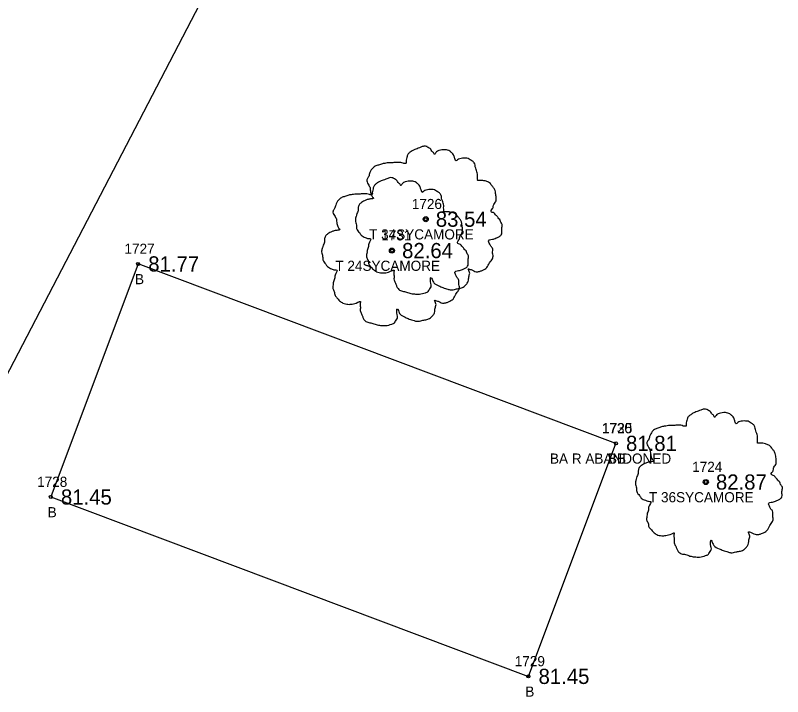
# Model space of a CAD drawing. Extents: x 2139392 to 2143384, y 505395 to 510520.
# Drawn here: x 2141179.8 to 2141255.5, y 509366.5 to 509433.7 of the extents above; entities that cross this region are included whole.
import ezdxf

# ---------------------------------------------------------------- set-up
doc = ezdxf.new("R2010")
doc.units = 0
for name, color, linetype in [('RD_EX_Bldg', 7, 'Continuous'), ('RD_EX_Bldg_txCode', 7, 'Continuous'), ('RD_EX_Fence_Other', 7, 'Continuous'), ('RD_EX_TX_Bldg_ELEV', 7, 'Continuous'), ('RD_EX_TX_VEG_ELEV', 7, 'Continuous'), ('RD_EX_VEG', 7, 'Continuous'), ('RD_EX_VEG_txCode', 7, 'Continuous'), ('RD_SMD_Locator', 7, 'Continuous')]:
    doc.layers.add(name, color=color, linetype=linetype)

msp = doc.modelspace()

# ---------------------------------------------------------------- linework, layer by layer
at = {"layer": 'RD_EX_Bldg'}
msp.add_lwpolyline([(2141239.059, 509391.502), (2141191.916, 509409.201), (2141183.3, 509386.211), (2141230.429, 509368.517), (2141239.059, 509391.502)], dxfattribs=at)
at = {"layer": 'RD_EX_Fence_Other'}
msp.add_lwpolyline([(2141244.956, 509535.084), (2141227.835, 509492.247), (2141166.832, 509374.977), (2141164.262, 509373.907), (2141120.57, 509389.846)], dxfattribs=at)
at = {"layer": 'RD_EX_VEG'}
for centre, radius in [((2141220.293, 509413.615), 0.25), ((2141220.28, 509413.596), 0.0001), ((2141216.967, 509410.519), 0.25), ((2141216.954, 509410.5), 0.0001), ((2141247.934, 509387.689), 0.25), ((2141247.921, 509387.67), 0.0001)]:
    msp.add_circle(centre, radius, dxfattribs=at)
for points in [[(2141220.425, 509420.782), (2141220.125, 509420.807), (2141219.8, 509420.707), (2141219.55, 509420.607), (2141219.325, 509420.532), (2141219.1, 509420.432), (2141218.8, 509420.257), (2141218.575, 509420.057), (2141218.45, 509419.807), (2141218.4, 509419.582), (2141218.351, 509419.308), (2141218.351, 509419.133), (2141218.226, 509419.108), (2141218.076, 509419.133), (2141217.826, 509419.208), (2141217.576, 509419.208), (2141217.326, 509419.208), (2141216.976, 509419.183), (2141216.626, 509419.183), (2141216.351, 509419.133), (2141216.027, 509419.083), (2141215.652, 509418.958), (2141215.302, 509418.833), (2141215.002, 509418.583), (2141214.752, 509418.108), (2141214.627, 509417.758), (2141214.477, 509417.508), (2141214.627, 509417.059), (2141214.802, 509416.709), (2141214.827, 509416.509), (2141214.902, 509416.084), (2141215.002, 509415.859), (2141215.127, 509415.659), (2141215.052, 509415.634), (2141214.677, 509415.584), (2141214.377, 509415.484), (2141213.952, 509415.259), (2141213.728, 509415.034), (2141213.628, 509414.709), (2141213.603, 509414.36), (2141213.503, 509414.16), (2141213.428, 509413.885), (2141213.403, 509413.81), (2141213.353, 509413.485), (2141213.453, 509413.035), (2141213.478, 509412.685), (2141213.603, 509412.46), (2141213.753, 509412.286), (2141213.927, 509412.036), (2141214.327, 509411.811), (2141214.652, 509411.711), (2141214.852, 509411.686), (2141214.677, 509411.186), (2141214.627, 509410.836), (2141214.502, 509410.436), (2141214.502, 509410.361), (2141214.452, 509409.887), (2141214.602, 509409.562), (2141214.677, 509409.187), (2141214.852, 509408.962), (2141215.127, 509408.662), (2141215.452, 509408.437), (2141215.952, 509408.312), (2141216.351, 509408.337), (2141216.926, 509408.512), (2141217.176, 509408.587), (2141217.151, 509408.412), (2141217.176, 509408.037), (2141217.176, 509407.613), (2141217.326, 509407.288), (2141217.426, 509407.013), (2141217.576, 509406.763), (2141217.901, 509406.538), (2141218.301, 509406.463), (2141218.725, 509406.313), (2141219.175, 509406.238), (2141219.675, 509406.213), (2141220.275, 509406.363), (2141220.55, 509406.488), (2141220.65, 509406.663), (2141220.849, 509407.038), (2141220.799, 509407.263), (2141220.824, 509407.863), (2141220.924, 509407.688), (2141221.099, 509407.338), (2141221.599, 509407.038), (2141221.999, 509406.863), (2141222.474, 509406.713), (2141222.774, 509406.638), (2141223.248, 509406.713), (2141223.623, 509406.788), (2141223.998, 509406.913), (2141224.298, 509407.188), (2141224.473, 509407.463), (2141224.523, 509407.738), (2141224.598, 509408.112), (2141224.648, 509408.287)], [(2141224.648, 509408.287), (2141224.573, 509408.462), (2141224.523, 509408.712), (2141224.598, 509408.687), (2141224.773, 509408.637), (2141225.048, 509408.512), (2141225.273, 509408.437), (2141225.597, 509408.462), (2141225.872, 509408.562), (2141226.322, 509408.837), (2141226.597, 509409.312), (2141226.872, 509409.712), (2141226.947, 509410.037), (2141226.897, 509410.261), (2141226.872, 509410.761), (2141226.672, 509411.011), (2141226.622, 509411.136), (2141226.522, 509411.536), (2141226.597, 509411.586), (2141226.872, 509411.636), (2141227.247, 509411.761), (2141227.522, 509411.886), (2141227.746, 509412.061), (2141227.821, 509412.286), (2141227.796, 509412.685), (2141227.846, 509413.085), (2141227.771, 509413.235), (2141227.671, 509413.385), (2141227.596, 509413.585), (2141227.447, 509413.735), (2141227.347, 509413.885), (2141227.247, 509413.985), (2141227.122, 509414.135), (2141226.947, 509414.26), (2141226.797, 509414.31), (2141226.747, 509414.46), (2141226.897, 509414.66), (2141226.947, 509414.759), (2141226.972, 509414.984), (2141227.197, 509415.334), (2141227.247, 509415.734), (2141227.197, 509416.159), (2141227.147, 509416.434), (2141226.997, 509416.709), (2141226.797, 509416.959), (2141226.672, 509417.133), (2141226.497, 509417.258), (2141226.172, 509417.383), (2141225.922, 509417.433), (2141225.572, 509417.433), (2141225.372, 509417.483), (2141225.397, 509417.533), (2141225.397, 509417.683), (2141225.397, 509417.958), (2141225.322, 509418.408), (2141225.173, 509418.908), (2141225.173, 509418.933), (2141225.073, 509419.183), (2141224.848, 509419.382), (2141224.673, 509419.482), (2141224.473, 509419.607), (2141224.223, 509419.632), (2141223.923, 509419.632), (2141223.648, 509419.582), (2141223.448, 509419.482), (2141223.273, 509419.357), (2141223.198, 509419.507), (2141223.098, 509419.807), (2141223.048, 509419.957), (2141222.899, 509420.132), (2141222.674, 509420.332), (2141222.224, 509420.457), (2141221.599, 509420.382), (2141221.299, 509420.182), (2141221.149, 509420.007), (2141221.099, 509420.132), (2141220.899, 509420.332), (2141220.799, 509420.507), (2141220.625, 509420.632), (2141220.475, 509420.732), (2141220.375, 509420.782)], [(2141217.099, 509417.687), (2141216.799, 509417.712), (2141216.474, 509417.612), (2141216.224, 509417.512), (2141215.999, 509417.437), (2141215.775, 509417.337), (2141215.475, 509417.162), (2141215.25, 509416.962), (2141215.125, 509416.712), (2141215.075, 509416.487), (2141215.025, 509416.212), (2141215.025, 509416.037), (2141214.9, 509416.012), (2141214.75, 509416.037), (2141214.5, 509416.112), (2141214.25, 509416.112), (2141214, 509416.112), (2141213.65, 509416.087), (2141213.301, 509416.087), (2141213.026, 509416.037), (2141212.701, 509415.987), (2141212.326, 509415.862), (2141211.976, 509415.737), (2141211.676, 509415.487), (2141211.426, 509415.013), (2141211.301, 509414.663), (2141211.152, 509414.413), (2141211.301, 509413.963), (2141211.476, 509413.613), (2141211.501, 509413.413), (2141211.576, 509412.989), (2141211.676, 509412.764), (2141211.801, 509412.564), (2141211.726, 509412.539), (2141211.351, 509412.489), (2141211.052, 509412.389), (2141210.627, 509412.164), (2141210.402, 509411.939), (2141210.302, 509411.614), (2141210.277, 509411.264), (2141210.177, 509411.064), (2141210.102, 509410.79), (2141210.077, 509410.715), (2141210.027, 509410.39), (2141210.127, 509409.94), (2141210.152, 509409.59), (2141210.277, 509409.365), (2141210.427, 509409.19), (2141210.602, 509408.94), (2141211.002, 509408.715), (2141211.326, 509408.615), (2141211.526, 509408.591), (2141211.351, 509408.091), (2141211.301, 509407.741), (2141211.177, 509407.341), (2141211.177, 509407.266), (2141211.127, 509406.791), (2141211.276, 509406.466), (2141211.351, 509406.092), (2141211.526, 509405.867), (2141211.801, 509405.567), (2141212.126, 509405.342), (2141212.626, 509405.217), (2141213.026, 509405.242), (2141213.601, 509405.417), (2141213.85, 509405.492), (2141213.825, 509405.317), (2141213.85, 509404.942), (2141213.85, 509404.517), (2141214, 509404.192), (2141214.1, 509403.918), (2141214.25, 509403.668), (2141214.575, 509403.443), (2141214.975, 509403.368), (2141215.4, 509403.218), (2141215.85, 509403.143), (2141216.349, 509403.118), (2141216.949, 509403.268), (2141217.224, 509403.393), (2141217.324, 509403.568), (2141217.524, 509403.943), (2141217.474, 509404.167), (2141217.499, 509404.767), (2141217.599, 509404.592), (2141217.774, 509404.242), (2141218.273, 509403.943), (2141218.673, 509403.768), (2141219.148, 509403.618), (2141219.448, 509403.543), (2141219.923, 509403.618), (2141220.298, 509403.693), (2141220.672, 509403.818), (2141220.972, 509404.092), (2141221.147, 509404.367), (2141221.197, 509404.642), (2141221.272, 509405.017), (2141221.322, 509405.192)], [(2141221.322, 509405.192), (2141221.247, 509405.367), (2141221.197, 509405.617), (2141221.272, 509405.592), (2141221.447, 509405.542), (2141221.722, 509405.417), (2141221.947, 509405.342), (2141222.272, 509405.367), (2141222.547, 509405.467), (2141222.996, 509405.742), (2141223.271, 509406.217), (2141223.546, 509406.616), (2141223.621, 509406.941), (2141223.571, 509407.166), (2141223.546, 509407.666), (2141223.346, 509407.916), (2141223.296, 509408.041), (2141223.196, 509408.441), (2141223.271, 509408.491), (2141223.546, 509408.541), (2141223.921, 509408.665), (2141224.196, 509408.79), (2141224.421, 509408.965), (2141224.496, 509409.19), (2141224.471, 509409.59), (2141224.521, 509409.99), (2141224.446, 509410.14), (2141224.346, 509410.29), (2141224.271, 509410.49), (2141224.121, 509410.64), (2141224.021, 509410.79), (2141223.921, 509410.889), (2141223.796, 509411.039), (2141223.621, 509411.164), (2141223.471, 509411.214), (2141223.421, 509411.364), (2141223.571, 509411.564), (2141223.621, 509411.664), (2141223.646, 509411.889), (2141223.871, 509412.239), (2141223.921, 509412.639), (2141223.871, 509413.064), (2141223.821, 509413.338), (2141223.671, 509413.613), (2141223.471, 509413.863), (2141223.346, 509414.038), (2141223.171, 509414.163), (2141222.846, 509414.288), (2141222.597, 509414.338), (2141222.247, 509414.338), (2141222.047, 509414.388), (2141222.072, 509414.438), (2141222.072, 509414.588), (2141222.072, 509414.863), (2141221.997, 509415.313), (2141221.847, 509415.812), (2141221.847, 509415.837), (2141221.747, 509416.087), (2141221.522, 509416.287), (2141221.347, 509416.387), (2141221.147, 509416.512), (2141220.897, 509416.537), (2141220.597, 509416.537), (2141220.323, 509416.487), (2141220.123, 509416.387), (2141219.948, 509416.262), (2141219.873, 509416.412), (2141219.773, 509416.712), (2141219.723, 509416.862), (2141219.573, 509417.037), (2141219.348, 509417.237), (2141218.898, 509417.362), (2141218.273, 509417.287), (2141217.974, 509417.087), (2141217.824, 509416.912), (2141217.774, 509417.037), (2141217.574, 509417.237), (2141217.474, 509417.412), (2141217.299, 509417.537), (2141217.149, 509417.637), (2141217.049, 509417.687)], [(2141248.065, 509394.856), (2141247.766, 509394.881), (2141247.441, 509394.781), (2141247.191, 509394.681), (2141246.966, 509394.606), (2141246.741, 509394.506), (2141246.441, 509394.331), (2141246.216, 509394.131), (2141246.091, 509393.882), (2141246.041, 509393.657), (2141245.991, 509393.382), (2141245.991, 509393.207), (2141245.866, 509393.182), (2141245.716, 509393.207), (2141245.467, 509393.282), (2141245.217, 509393.282), (2141244.967, 509393.282), (2141244.617, 509393.257), (2141244.267, 509393.257), (2141243.992, 509393.207), (2141243.667, 509393.157), (2141243.292, 509393.032), (2141242.943, 509392.907), (2141242.643, 509392.657), (2141242.393, 509392.182), (2141242.268, 509391.832), (2141242.118, 509391.583), (2141242.268, 509391.133), (2141242.443, 509390.783), (2141242.468, 509390.583), (2141242.543, 509390.158), (2141242.643, 509389.933), (2141242.768, 509389.733), (2141242.693, 509389.708), (2141242.318, 509389.658), (2141242.018, 509389.558), (2141241.593, 509389.334), (2141241.368, 509389.109), (2141241.268, 509388.784), (2141241.243, 509388.434), (2141241.143, 509388.234), (2141241.069, 509387.959), (2141241.044, 509387.884), (2141240.993, 509387.559), (2141241.093, 509387.109), (2141241.118, 509386.76), (2141241.243, 509386.535), (2141241.393, 509386.36), (2141241.568, 509386.11), (2141241.968, 509385.885), (2141242.293, 509385.785), (2141242.493, 509385.76), (2141242.318, 509385.26), (2141242.268, 509384.91), (2141242.143, 509384.511), (2141242.143, 509384.436), (2141242.093, 509383.961), (2141242.243, 509383.636), (2141242.318, 509383.261), (2141242.493, 509383.036), (2141242.768, 509382.736), (2141243.093, 509382.512), (2141243.592, 509382.387), (2141243.992, 509382.412), (2141244.567, 509382.586), (2141244.817, 509382.661), (2141244.792, 509382.487), (2141244.817, 509382.112), (2141244.817, 509381.687), (2141244.967, 509381.362), (2141245.067, 509381.087), (2141245.217, 509380.837), (2141245.542, 509380.612), (2141245.941, 509380.537), (2141246.366, 509380.387), (2141246.816, 509380.312), (2141247.316, 509380.287), (2141247.916, 509380.437), (2141248.19, 509380.562), (2141248.29, 509380.737), (2141248.49, 509381.112), (2141248.44, 509381.337), (2141248.465, 509381.937), (2141248.565, 509381.762), (2141248.74, 509381.412), (2141249.24, 509381.112), (2141249.64, 509380.937), (2141250.115, 509380.787), (2141250.414, 509380.712), (2141250.889, 509380.787), (2141251.264, 509380.862), (2141251.639, 509380.987), (2141251.939, 509381.262), (2141252.114, 509381.537), (2141252.164, 509381.812), (2141252.239, 509382.187), (2141252.289, 509382.362)], [(2141252.289, 509382.362), (2141252.214, 509382.537), (2141252.164, 509382.786), (2141252.239, 509382.761), (2141252.413, 509382.711), (2141252.688, 509382.586), (2141252.913, 509382.512), (2141253.238, 509382.537), (2141253.513, 509382.636), (2141253.963, 509382.911), (2141254.238, 509383.386), (2141254.513, 509383.786), (2141254.588, 509384.111), (2141254.538, 509384.336), (2141254.513, 509384.835), (2141254.313, 509385.085), (2141254.263, 509385.21), (2141254.163, 509385.61), (2141254.238, 509385.66), (2141254.513, 509385.71), (2141254.887, 509385.835), (2141255.162, 509385.96), (2141255.387, 509386.135), (2141255.462, 509386.36), (2141255.437, 509386.76), (2141255.487, 509387.159), (2141255.412, 509387.309), (2141255.312, 509387.459), (2141255.237, 509387.659), (2141255.087, 509387.809), (2141254.987, 509387.959), (2141254.887, 509388.059), (2141254.763, 509388.209), (2141254.588, 509388.334), (2141254.438, 509388.384), (2141254.388, 509388.534), (2141254.538, 509388.734), (2141254.588, 509388.834), (2141254.612, 509389.059), (2141254.837, 509389.408), (2141254.887, 509389.808), (2141254.837, 509390.233), (2141254.788, 509390.508), (2141254.638, 509390.783), (2141254.438, 509391.033), (2141254.313, 509391.208), (2141254.138, 509391.333), (2141253.813, 509391.458), (2141253.563, 509391.508), (2141253.213, 509391.508), (2141253.013, 509391.558), (2141253.038, 509391.608), (2141253.038, 509391.757), (2141253.038, 509392.032), (2141252.963, 509392.482), (2141252.813, 509392.982), (2141252.813, 509393.007), (2141252.713, 509393.257), (2141252.488, 509393.457), (2141252.314, 509393.557), (2141252.114, 509393.682), (2141251.864, 509393.707), (2141251.564, 509393.707), (2141251.289, 509393.657), (2141251.089, 509393.557), (2141250.914, 509393.432), (2141250.839, 509393.582), (2141250.739, 509393.882), (2141250.689, 509394.031), (2141250.539, 509394.206), (2141250.314, 509394.406), (2141249.865, 509394.531), (2141249.24, 509394.456), (2141248.94, 509394.256), (2141248.79, 509394.081), (2141248.74, 509394.206), (2141248.54, 509394.406), (2141248.44, 509394.581), (2141248.265, 509394.706), (2141248.115, 509394.806), (2141248.015, 509394.856)]]:
    msp.add_spline(points, degree=3, dxfattribs=at)
at = {"layer": 'RD_SMD_Locator'}
for centre in [(2141220.293, 509413.615), (2141216.967, 509410.519), (2141191.916, 509409.201), (2141239.059, 509391.502), (2141239.059, 509391.502), (2141247.933, 509387.689), (2141183.3, 509386.211), (2141230.429, 509368.517)]:
    msp.add_circle(centre, 0.15, dxfattribs=at)

# ---------------------------------------------------------------- texts
at = {"layer": 'RD_EX_Bldg_txCode'}
for s, p in [('1727', (2141190.569, 509410.201)), ('B', (2141191.609, 509407.201)), ('1730', (2141237.673, 509392.502)), ('1725', (2141237.712, 509392.502)), ('BA R ABANDONED', (2141232.555, 509389.502)), ('BB', (2141238.279, 509389.502)), ('1728', (2141181.954, 509387.211)), ('B', (2141182.993, 509384.211)), ('1729', (2141229.083, 509369.517)), ('B', (2141230.122, 509366.517))]:
    msp.add_text(s, height=1, dxfattribs=at).set_placement(p)
at = {"layer": 'RD_EX_TX_Bldg_ELEV'}
for s, p in [('81.77', (2141192.916, 509408.451)), ('81.81', (2141240.059, 509390.752)), ('81.81', (2141240.059, 509390.752)), ('81.45', (2141184.3, 509385.461)), ('81.45', (2141231.429, 509367.767))]:
    msp.add_text(s, height=1.5, dxfattribs=at).set_placement(p)
at = {"layer": 'RD_EX_TX_VEG_ELEV'}
for s, p in [('83.54', (2141221.293, 509412.865)), ('82.64', (2141217.967, 509409.769)), ('82.87', (2141248.933, 509386.939))]:
    msp.add_text(s, height=1.5, dxfattribs=at).set_placement(p)
at = {"layer": 'RD_EX_VEG_txCode'}
for s, p in [('1726', (2141218.923, 509414.615)), ('T 34SYCAMORE', (2141214.706, 509411.615)), ('1731', (2141215.904, 509411.519)), ('T 24SYCAMORE', (2141211.38, 509408.519)), ('1724', (2141246.587, 509388.689)), ('T 36SYCAMORE', (2141242.323, 509385.689))]:
    msp.add_text(s, height=1, dxfattribs=at).set_placement(p)

doc.saveas('drawing.dxf')
